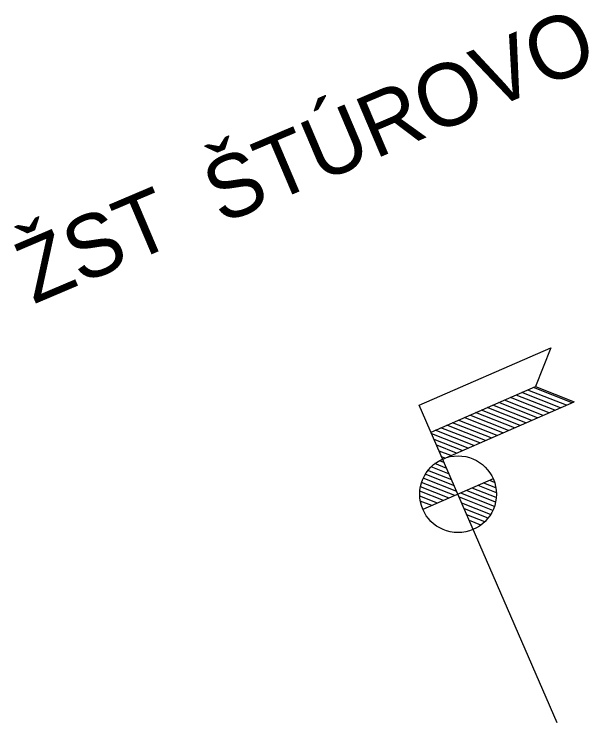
# Model space of a CAD drawing. Extents: x -566241 to -448637, y -1329577 to -1274522.
# Drawn here: x -460991 to -460346, y -1329577 to -1328783 of the extents above; entities that cross this region are included whole.
import ezdxf

# ---------------------------------------------------------------- set-up
doc = ezdxf.new("R2010")
doc.units = 0
doc.layers.add('DOPRAVNE', color=7, linetype='Continuous')
doc.layers.add('DOPRAVNE NAZOV', color=7, linetype='Continuous')

msp = doc.modelspace()

# ---------------------------------------------------------------- linework, layer by layer
at = {"layer": 'DOPRAVNE'}
for p, q in [((-460536.5, -1329220.69), (-460389.13, -1329156.67)), ((-460389.13, -1329156.67), (-460406.26, -1329200.11)), ((-460523.34, -1329250.97), (-460406.26, -1329200.11)), ((-460365.03, -1329218.2), (-460408.47, -1329201.07)), ((-460406.26, -1329200.11), (-460362.82, -1329217.24)), ((-460378.01, -1329223.83), (-460421.44, -1329206.71)), ((-460371.52, -1329221.01), (-460414.96, -1329203.89)), ((-460397.46, -1329232.28), (-460440.9, -1329215.16)), ((-460390.98, -1329229.47), (-460434.41, -1329212.34)), ((-460384.49, -1329226.65), (-460427.93, -1329209.52)), ((-460381.71, -1329577), (-460536.5, -1329220.69)), ((-460510.19, -1329281.25), (-460362.82, -1329217.24)), ((-460416.92, -1329240.74), (-460460.35, -1329223.61)), ((-460410.43, -1329237.92), (-460453.87, -1329220.79)), ((-460403.95, -1329235.1), (-460447.38, -1329217.98)), ((-460436.38, -1329249.19), (-460479.81, -1329232.06)), ((-460429.89, -1329246.37), (-460473.33, -1329229.25)), ((-460423.4, -1329243.55), (-460466.84, -1329226.43)), ((-460455.83, -1329257.64), (-460499.27, -1329240.52)), ((-460449.35, -1329254.82), (-460492.78, -1329237.7)), ((-460442.86, -1329252.01), (-460486.3, -1329234.88)), ((-460468.8, -1329263.28), (-460512.24, -1329246.15)), ((-460462.32, -1329260.46), (-460505.75, -1329243.33)), ((-460481.77, -1329268.91), (-460522.53, -1329252.84)), ((-460475.29, -1329266.09), (-460518.72, -1329248.97)), ((-460488.26, -1329271.73), (-460519.72, -1329259.33)), ((-460494.75, -1329274.55), (-460516.9, -1329265.81)), ((-460494.75, -1329274.55), (-460516.9, -1329265.81)), ((-460501.23, -1329277.36), (-460514.08, -1329272.3)), ((-460501.23, -1329277.36), (-460514.08, -1329272.3)), ((-460507.72, -1329280.18), (-460511.26, -1329278.78)), ((-460507.72, -1329280.18), (-460511.26, -1329278.78)), ((-460505.63, -1329291.75), (-460519.07, -1329286.45)), ((-460508.45, -1329285.27), (-460513.94, -1329283.1)), ((-460499.99, -1329304.72), (-460526.87, -1329294.13)), ((-460502.81, -1329298.24), (-460523.32, -1329290.15)), ((-460453.59, -1329303.57), (-460532.51, -1329337.85)), ((-460494.36, -1329317.7), (-460532.16, -1329302.79)), ((-460497.18, -1329311.21), (-460529.8, -1329298.35)), ((-460503, -1329325.04), (-460535.24, -1329312.32)), ((-460496.52, -1329322.22), (-460533.97, -1329307.45)), ((-460450.06, -1329319.04), (-460470.58, -1329310.95)), ((-460450.65, -1329313.43), (-460464.09, -1329308.13)), ((-460452.12, -1329307.48), (-460457.6, -1329305.31)), ((-460509.49, -1329327.85), (-460535.94, -1329317.42)), ((-460452.23, -1329334.31), (-460490.03, -1329319.4)), ((-460450.93, -1329329.45), (-460483.55, -1329316.58)), ((-460450.18, -1329324.36), (-460477.06, -1329313.77)), ((-460515.97, -1329330.67), (-460536.02, -1329322.77)), ((-460522.46, -1329333.49), (-460535.38, -1329328.4)), ((-460454.09, -1329338.95), (-460491.54, -1329324.18)), ((-460456.48, -1329343.38), (-460488.72, -1329330.67)), ((-460459.45, -1329347.58), (-460485.91, -1329337.15)), ((-460463.04, -1329351.54), (-460483.09, -1329343.64)), ((-460467.36, -1329355.22), (-460480.27, -1329350.12))]:
    msp.add_line(p, q, dxfattribs=at)
msp.add_circle((-460493.05, -1329320.71), 43.02, dxfattribs=at)

# ---------------------------------------------------------------- texts
at = {"layer": 'DOPRAVNE NAZOV'}
msp.add_text('ŽST  ŠTÚROVO', height=70, rotation=23.02825, dxfattribs=at).set_placement((-460969.28, -1329108.08))

doc.saveas('drawing.dxf')
